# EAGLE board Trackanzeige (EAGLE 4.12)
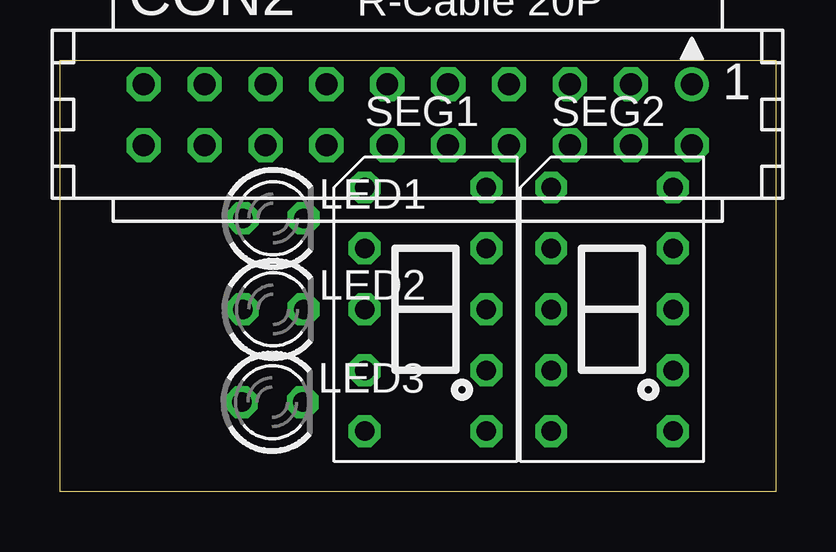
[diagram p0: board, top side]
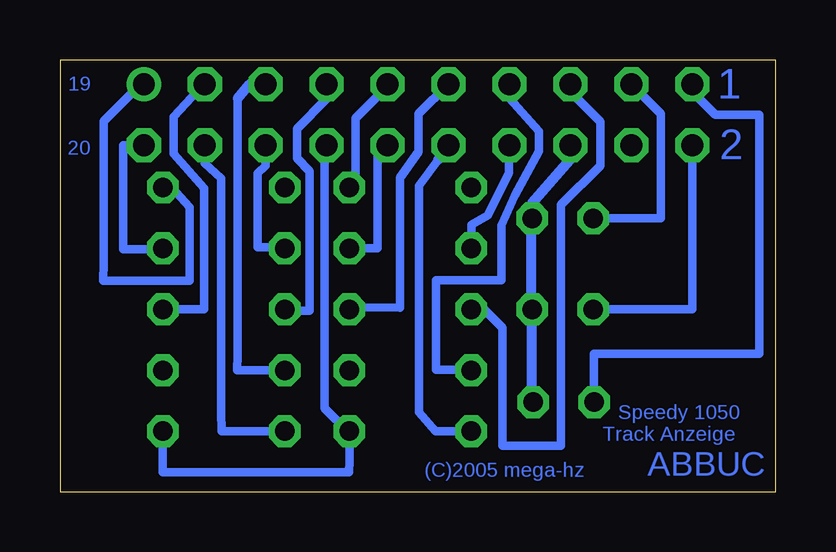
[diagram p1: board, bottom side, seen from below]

Size 29.85 x 17.98 mm. Coordinates in mm from the lower left corner, seen from the top.
Outline: 0,17.98 29.84,17.98 29.84,0 0,0 0,17.98
Copper layers (1*16): Top 0.035mm / dielectric 1.5mm / Bottom 0.035mm
Design rules "default": minimum track width 10mil, minimum drill 24mil, track to track 8mil, track to pad 8mil, pad to pad 8mil, via to via 8mil, smd to smd 8mil, copper to edge 40mil, drill to drill 8mil, minimum pad ring 10mil, minimum via ring 8mil, stop-mask expansion 4mil, vias tented up to drill 0mil, thermal gap 10mil

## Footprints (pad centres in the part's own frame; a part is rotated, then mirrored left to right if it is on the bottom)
CON20L = drill 0.914 round: 1 11.43,1.27 | drill 0.914 octagon: 2 11.43,-1.27; 3 8.89,1.27; 4 8.89,-1.27; 5 6.35,1.27; 6 6.35,-1.27; 7 3.81,1.27; 8 3.81,-1.27; 9 1.27,1.27; 10 1.27,-1.27; 11 -1.27,1.27; 12 -1.27,-1.27; 13 -3.81,1.27; 14 -3.81,-1.27; 15 -6.35,1.27; 16 -6.35,-1.27; 17 -8.89,1.27; 18 -8.89,-1.27; 19 -11.43,1.27; 20 -11.43,-1.27
LED3MM = drill 0.813 octagon: A -1.27,0; K 1.27,0
HDSP-XXX = drill 0.813 octagon: 1 -2.54,5.08; 2 -2.54,2.54; 3 -2.54,0; 4 -2.54,-2.54; 5 -2.54,-5.08; 6 2.54,-5.08; 7 2.54,-2.54; 8 2.54,0; 9 2.54,2.54; 10 2.54,5.08

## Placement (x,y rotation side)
CON2  [CON20L]  14.92,15.71 0 top
LED1  [LED3MM]  8.89,11.38 0 top
LED2  [LED3MM]  8.89,7.59 0 top
LED3  [LED3MM]  8.85,3.72 0 top
SEG1  [HDSP-XXX]  15.24,7.59 0 top
SEG2  [HDSP-XXX]  23.02,7.59 0 top

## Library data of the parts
CON2 = con-harting
LED1-LED3 = led
SEG1 SEG2 = straschu-aktiv

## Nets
N$61: CON2.8 SEG1.6 SEG2.6
N$62: CON2.19 LED3.A
N$63: CON2.20 LED2.A
N$65: CON2.17 LED1.A
N$66: CON2.15 SEG1.3
N$67: CON2.13 SEG1.4
N$68: CON2.11 SEG1.8
N$69: CON2.9 SEG1.10
N$70: CON2.7 SEG2.3
N$71: CON2.5 SEG2.4
N$72: CON2.3 SEG2.8
N$73: CON2.1 SEG2.10
N$74: CON2.16 LED1.K LED2.K LED3.K
N$75: CON2.14 SEG1.2
N$76: CON2.12 SEG1.5
N$77: CON2.10 SEG1.9
N$79: CON2.6 SEG2.2
N$80: CON2.4 SEG2.5
N$81: CON2.2 SEG2.9

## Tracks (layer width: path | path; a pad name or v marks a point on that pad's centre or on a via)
N$61
  Bottom 0.356: 18.73,14.4 CON2.8 | 18.82,14.33 18.82,3.47 17.81,2.49 | SEG1.6 17.78,1.29 17.79,0.8 25.55,0.8 25.55,2.44 | 25.56,2.44 SEG2.6
  Bottom 0.406: 18.82,14.33 18.73,14.4 | 17.81,2.49 SEG1.6 | 25.55,2.44 25.56,2.44
N$62
  Bottom 0.356: LED3.A 7.58,5.74 0.68,5.74 0.68,15.71 2.51,15.71 3.46,16.65 3.46,16.99 CON2.19
N$63
  Bottom 0.356: CON2.20 3.48,7.6 7.59,7.6 LED2.A
N$65
  Bottom 0.356: CON2.17 4.78,15.73 4.78,11.39 LED1.A
N$66
  Bottom 0.356: CON2.15 8.57,16.67 7.32,15.42 7.32,13.58 8.96,11.94 8.96,1.91 11.39,1.91 11.39,6.83 12.16,7.6 12.67,7.6 12.68,7.6 SEG1.3
N$67
  Bottom 0.356: CON2.13 11.11,16.38 9.87,15.01 9.87,14.19 10.89,12.35 11.44,11.1 11.44,8.81 11.56,8.81 14.17,8.81 14.17,5.5 14.17,5.07 12.79,5.07 12.78,5.05 SEG1.4
N$68
  Bottom 0.356: CON2.11 14.89,15.75 14.89,14.16 15.67,13.09 15.67,7.66 17.27,7.68 17.9,7.68 | SEG1.8 17.87,7.6
  Bottom 0.406: CON2.11 | 17.87,7.6 17.93,7.65 17.9,7.68
N$69
  Bottom 0.356: CON2.9 16.19,16.89 17.52,15.56 17.52,12.99 17.78,12.73 SEG1.10
N$70
  Bottom 0.356: CON2.7 18.73,16.36 19.97,15.12 19.97,13.9 19.44,13.34 19.44,7.53 19.97,7.53 20.44,7.53 20.5,7.59
  Bottom 0.406: 20.5,7.59 20.5,7.6 SEG2.3
N$71
  Bottom 0.356: 22.44,16.37 22.44,5.71 22.45,5.05 20.44,5.05
  Bottom 0.406: CON2.5 21.94,16.98 22.44,16.37 | 20.44,5.05 20.45,5.05 SEG2.4
N$72
  Bottom 0.356: 23.85,16.98 25.11,15.62 25.11,14.08 23.83,12.64 23.83,7.61 25.39,7.6 SEG2.8
  Bottom 0.406: 23.85,16.98 CON2.3
N$73
  Bottom 0.356: CON2.1 26.49,16.98 28.03,15.43 28.03,9.53 28.05,8.78 25.08,8.78 24.43,8.78 24.43,11.85 25.18,12.67 SEG2.10
N$74
  Bottom 0.406: 10.16,12.02 10.19,11.34 10.19,7.53 10.16,7.55 LED2.K 10.16,3.72 | 10.16,12.02 LED1.K | CON2.16 8.57,13.85 10.16,12.02 | 10.16,3.72 10.15,3.72 LED3.K | 10.16,3.72
N$75
  Bottom 0.356: CON2.14 11.13,13.29 12,11.51 12.7,11.12 12.7,10.15 SEG1.2
N$76
  Bottom 0.356: 14.08,13.84 CON2.12 | 14.04,13.86 14.89,12.75 14.89,3.3 14.2,2.51 12.63,2.51
  Bottom 0.406: CON2.12 | 14.04,13.86 14.08,13.84 | 12.63,2.51 12.64,2.51 SEG1.5
N$77
  Bottom 0.356: 17.8,10.14 16.61,10.13 16.61,14.06 16.23,14.44
  Bottom 0.406: 17.81,10.13 17.8,10.14 SEG1.9 | 16.23,14.44 CON2.10
N$79
  Bottom 0.356: CON2.6 21.27,13.57 21.61,13.27 21.61,10.7 21.61,10.18 20.53,10.18
  Bottom 0.406: SEG2.2 20.47,10.14 20.44,10.16 20.53,10.18
N$80
  Bottom 0.356: CON2.4 23.81,13.68 23.13,13.05 23.13,3.32 23.11,2.51 20.5,2.51
  Bottom 0.406: 20.48,2.48 20.47,2.48 | SEG2.5 20.48,2.48 | 20.48,2.48 20.5,2.51
N$81
  Bottom 0.356: CON2.2 27.21,14.44 27.21,10.1 25.5,10.1
  Bottom 0.406: 25.5,10.1 25.5,10.14 SEG2.9

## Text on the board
Bottom: 19 | 1 | 2 | 20 | Speedy 1050 | Track Anzeige | ABBUC | (C)2005 mega-hz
